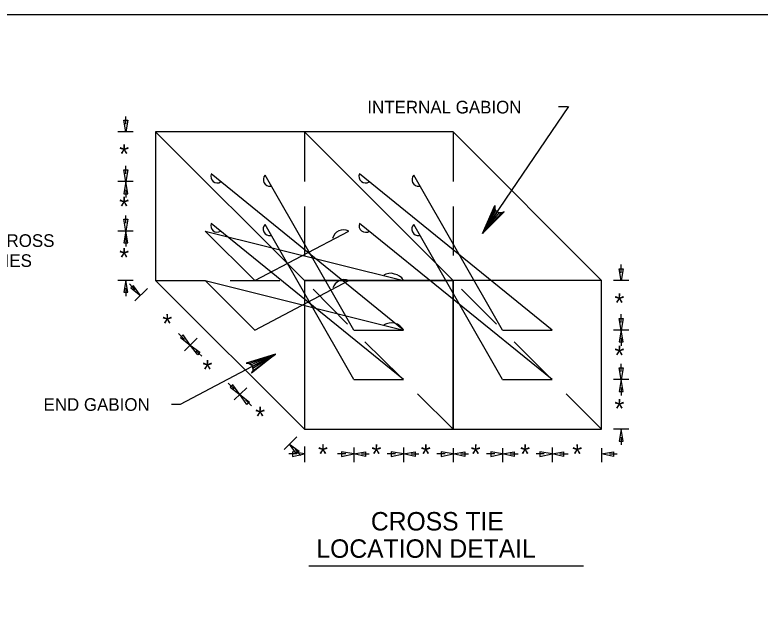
# Model space of a CAD drawing. Extents: x 3 to 3592, y -602 to 1171.
# Drawn here: x 1086.4 to 1263.1, y 421.8 to 561.8 of the extents above; entities that cross this region are included whole.
import ezdxf

# ---------------------------------------------------------------- set-up
doc = ezdxf.new("R2010")
doc.units = 0
for name, color, linetype in [('1', 7, 'Continuous'), ('2', 7, 'Continuous'), ('3', 7, 'Continuous'), ('H', 7, 'Continuous'), ('P', 7, 'Continuous')]:
    doc.layers.add(name, color=color, linetype=linetype)

msp = doc.modelspace()

# ---------------------------------------------------------------- linework, layer by layer
at = {"layer": '1'}
msp.add_lwpolyline([(1668.51, -2.17), (1668.51, 561.83), (882.51, 561.83), (882.51, -2.17), (1668.51, -2.17), (1668.51, 24.19), (1468.51, 24.19), (1468.51, 88.87), (1668.51, 88.87), (1668.51, 117.83), (1468.51, 117.83), (1468.51, -2.17), (1547.31, -2.17), (1547.31, 24.19), (1547.31, -2.17), (1624.31, -2.17), (1624.31, 24.19), (1624.31, 11.88), (1668.51, 11.88)], dxfattribs=at)
for centre, radius, start, end in [((1134.36, 523.51), 1.53, 160.1506, 301.2706), ((1146.84, 522.74), 1.57, 135.9148, 277.2153), ((1169.56, 523.55), 1.6, 158.8193, 302.0614), ((1182.1, 522.74), 1.57, 135.9148, 277.2153), ((1134.36, 511.82), 1.53, 160.1506, 301.2706), ((1146.79, 511.02), 1.55, 133.6678, 279.4623), ((1164.28, 508.18), 2.66, 61.7948, 166.7649), ((1169.55, 511.83), 1.57, 160.8674, 303.0386), ((1182.04, 511.02), 1.55, 133.6678, 279.4623), ((1164.5, 496.2), 2.83, 68.5264, 162.5936), ((1175.62, 485.43), 3.34, 28.9849, 121.7734)]:
    msp.add_arc(centre, radius, start, end, dxfattribs=at)
at = {"layer": '2'}
for points in [[(1197.29, 509.96), (1200.19, 516.61), (1200.2, 515.94), (1197.29, 509.96), (1200.43, 515.44), (1200.78, 515.1), (1197.29, 509.96), (1201.22, 514.9), (1201.78, 514.87), (1197.29, 509.96), (1202.4, 515.11), (1201.78, 514.87), (1201.22, 514.9), (1200.78, 515.1), (1200.43, 515.44), (1200.2, 515.94)], [(1148.17, 481.35), (1142.5, 476.82), (1142.81, 477.42), (1148.17, 481.35), (1142.83, 477.97), (1142.68, 478.43), (1148.17, 481.35), (1142.39, 478.82), (1141.91, 479.11), (1148.17, 481.35), (1141.25, 479.19), (1141.91, 479.11), (1142.39, 478.82), (1142.68, 478.43), (1142.83, 477.97), (1142.81, 477.42)]]:
    msp.add_lwpolyline(points, dxfattribs=at)
at = {"layer": '3'}
msp.add_line((1156.11, 431.12), (1221.23, 431.12), dxfattribs=at)
at = {"layer": 'H'}
for p, q in [((1112.24, 536.83), (1113.16, 536.83)), ((1112.7, 534.09), (1112.24, 536.83)), ((1113.16, 536.83), (1112.7, 534.09)), ((1112.24, 525.04), (1113.16, 525.04)), ((1112.7, 522.3), (1112.24, 525.04)), ((1113.16, 525.04), (1112.7, 522.3)), ((1112.7, 522.3), (1112.24, 519.41)), ((1113.16, 519.41), (1112.7, 522.3)), ((1112.24, 519.41), (1113.16, 519.41)), ((1112.24, 513.41), (1113.16, 513.41)), ((1112.7, 510.52), (1112.24, 513.41)), ((1113.16, 513.41), (1112.7, 510.52)), ((1112.7, 510.52), (1112.24, 507.77)), ((1113.16, 507.77), (1112.7, 510.52)), ((1112.24, 507.77), (1113.16, 507.77)), ((1229.69, 501.58), (1230.61, 501.58)), ((1230.15, 498.83), (1229.69, 501.58)), ((1230.61, 501.58), (1230.15, 498.83)), ((1112.7, 498.83), (1112.24, 496.09)), ((1113.16, 496.09), (1112.7, 498.83)), ((1114.48, 497.55), (1113.87, 497.1)), ((1113.87, 497.1), (1116.16, 495.27)), ((1116.16, 495.27), (1114.48, 497.55)), ((1112.24, 496.09), (1113.16, 496.09)), ((1229.69, 489.79), (1230.61, 489.79)), ((1230.15, 487.05), (1229.69, 489.79)), ((1230.61, 489.79), (1230.15, 487.05)), ((1230.15, 487.05), (1229.69, 484.3)), ((1230.61, 484.3), (1230.15, 487.05)), ((1126.26, 485.93), (1125.65, 485.32)), ((1125.65, 485.32), (1127.94, 483.49)), ((1127.94, 483.49), (1126.26, 485.93)), ((1229.69, 484.3), (1230.61, 484.3)), ((1129.77, 481.2), (1127.94, 483.49)), ((1127.94, 483.49), (1130.23, 481.81)), ((1130.23, 481.81), (1129.77, 481.2)), ((1229.69, 478.11), (1230.61, 478.11)), ((1230.15, 475.36), (1229.69, 478.11)), ((1230.61, 478.11), (1230.15, 475.36)), ((1138.05, 474.09), (1137.44, 473.48)), ((1139.72, 471.81), (1138.05, 474.09)), ((1230.15, 475.36), (1229.69, 472.47)), ((1230.61, 472.47), (1230.15, 475.36)), ((1137.44, 473.48), (1139.72, 471.81)), ((1229.69, 472.47), (1230.61, 472.47)), ((1141.4, 469.37), (1139.72, 471.81)), ((1139.72, 471.81), (1142.01, 469.98)), ((1142.01, 469.98), (1141.4, 469.37)), ((1230.15, 463.58), (1229.69, 460.68)), ((1230.61, 460.68), (1230.15, 463.58)), ((1153.19, 457.73), (1151.51, 460.02)), ((1151.51, 460.02), (1153.8, 458.34)), ((1229.69, 460.68), (1230.61, 460.68)), ((1152.17, 458.14), (1152.17, 457.07)), ((1155.07, 457.68), (1152.17, 458.14)), ((1153.8, 458.34), (1153.19, 457.73)), ((1163.85, 458.14), (1163.85, 457.07)), ((1166.75, 457.68), (1163.85, 458.14)), ((1166.75, 457.68), (1169.49, 458.14)), ((1169.49, 458.14), (1169.49, 457.07)), ((1175.64, 458.14), (1175.64, 457.07)), ((1178.54, 457.68), (1175.64, 458.14)), ((1178.54, 457.68), (1181.28, 458.14)), ((1181.28, 458.14), (1181.28, 457.07)), ((1187.43, 458.14), (1187.43, 457.07)), ((1190.32, 457.68), (1187.43, 458.14)), ((1190.32, 457.68), (1193.06, 458.14)), ((1193.06, 458.14), (1193.06, 457.07)), ((1199.26, 458.14), (1199.26, 457.07)), ((1202.01, 457.68), (1199.26, 458.14)), ((1202.01, 457.68), (1204.75, 458.14)), ((1204.75, 458.14), (1204.75, 457.07)), ((1210.9, 458.14), (1210.9, 457.07)), ((1213.79, 457.68), (1210.9, 458.14)), ((1213.78, 457.68), (1216.52, 458.14)), ((1216.52, 458.14), (1216.52, 457.07)), ((1225.48, 457.68), (1228.37, 458.14)), ((1228.37, 458.14), (1228.37, 457.07)), ((1152.17, 457.07), (1155.07, 457.68)), ((1163.85, 457.07), (1166.75, 457.68)), ((1169.49, 457.07), (1166.75, 457.68)), ((1175.64, 457.07), (1178.54, 457.68)), ((1181.28, 457.07), (1178.54, 457.68)), ((1187.43, 457.07), (1190.32, 457.68)), ((1193.06, 457.07), (1190.32, 457.68)), ((1199.26, 457.07), (1202.01, 457.68)), ((1204.75, 457.07), (1202.01, 457.68)), ((1210.9, 457.07), (1213.79, 457.68)), ((1216.52, 457.07), (1213.78, 457.68)), ((1228.37, 457.07), (1225.48, 457.68))]:
    msp.add_line(p, q, dxfattribs=at)
at = {"layer": 'P'}
for points in [[(1197.29, 509.96), (1217.75, 540.08)], [(1215.32, 540.08), (1217.45, 540.08)], [(1112.7, 535.92), (1112.7, 537.74)], [(1114.43, 534.09), (1110.77, 534.09)], [(1155.07, 534.09), (1119.71, 534.09)], [(1119.71, 534.09), (1119.71, 498.83)], [(1119.71, 534.09), (1155.07, 498.83)], [(1190.32, 534.09), (1155.07, 534.09)], [(1155.07, 534.09), (1190.32, 498.83)], [(1155.07, 534.09), (1155.07, 522.3)], [(1190.32, 534.09), (1225.48, 498.83)], [(1190.32, 534.09), (1190.32, 522.3)], [(1112.7, 524.13), (1112.7, 526.06)], [(1178.54, 487.05), (1132.92, 524.13)], [(1166.75, 487.05), (1145.72, 523.83)], [(1213.79, 487.05), (1168.07, 524.13)], [(1202.01, 487.05), (1180.97, 523.83)], [(1114.43, 522.3), (1110.77, 522.3)], [(1114.43, 522.3), (1110.77, 522.3)], [(1112.7, 520.37), (1112.7, 518.54)], [(1155.07, 516.41), (1155.07, 504.72)], [(1190.32, 516.41), (1190.32, 504.72)], [(1112.7, 512.45), (1112.7, 514.28)], [(1178.54, 475.36), (1132.92, 512.34)], [(1166.75, 475.36), (1145.72, 512.14)], [(1213.79, 475.36), (1168.07, 512.34)], [(1202.01, 475.36), (1180.97, 512.14)], [(1114.43, 510.52), (1110.77, 510.52)], [(1114.43, 510.52), (1110.77, 510.52)], [(1112.7, 510.52), (1112.7, 506.86)], [(1143.28, 498.83), (1131.5, 510.52)], [(1131.5, 510.52), (1178.54, 498.83)], [(1143.28, 498.83), (1165.53, 510.52)], [(1230.15, 500.66), (1230.15, 502.59)], [(1178.54, 498.83), (1178.13, 499.44), (1177.62, 499.85), (1177.01, 500.15), (1176.4, 500.36), (1175.69, 500.56), (1175.08, 500.46), (1174.37, 500.36), (1173.86, 500.05)], [(1114.43, 498.83), (1110.77, 498.83)], [(1119.71, 498.83), (1155.07, 463.58)], [(1119.71, 498.83), (1131.5, 498.83)], [(1143.28, 487.05), (1131.5, 498.83)], [(1131.5, 498.83), (1178.54, 487.05)], [(1137.39, 498.83), (1149.17, 498.83)], [(1143.28, 487.05), (1165.53, 498.83)], [(1190.32, 498.83), (1155.07, 498.83)], [(1155.07, 498.83), (1155.07, 463.58)], [(1155.07, 498.83), (1190.32, 498.83)], [(1190.32, 463.58), (1190.32, 498.83)], [(1225.48, 498.83), (1190.32, 498.83)], [(1190.32, 498.83), (1190.32, 463.58)], [(1225.48, 463.58), (1225.48, 498.83)], [(1231.98, 498.83), (1228.32, 498.83)], [(1112.7, 497), (1112.7, 495.07)], [(1114.83, 496.6), (1113.51, 498.02)], [(1117.78, 496.9), (1114.83, 493.96)], [(1165.23, 488.47), (1157.1, 496.8)], [(1200.58, 488.47), (1192.25, 496.8)], [(1230.15, 488.88), (1230.15, 490.81)], [(1126.62, 484.81), (1125.2, 486.23)], [(1166.75, 487.05), (1178.54, 487.05)], [(1202.01, 487.05), (1213.79, 487.05)], [(1231.98, 487.05), (1228.32, 487.05)], [(1231.98, 487.05), (1228.32, 487.05)], [(1129.56, 485.12), (1126.62, 482.17)], [(1177.72, 476.07), (1169.39, 484.3)], [(1212.98, 476.07), (1204.75, 484.3)], [(1230.15, 485.22), (1230.15, 483.29)], [(1128.24, 483.8), (1126.62, 482.17)], [(1148.17, 481.35), (1125.6, 469.37)], [(1129.26, 482.17), (1130.68, 480.85)], [(1230.15, 477.19), (1230.15, 479.02)], [(1138.4, 473.13), (1136.98, 474.45)], [(1166.75, 475.36), (1178.54, 475.36)], [(1202.01, 475.36), (1213.79, 475.36)], [(1231.98, 475.36), (1228.32, 475.36)], [(1231.98, 475.36), (1228.32, 475.36)], [(1141.35, 473.33), (1138.4, 470.49)], [(1190.32, 463.58), (1181.89, 471.91)], [(1225.48, 463.58), (1217.14, 471.91)], [(1230.15, 473.43), (1230.15, 471.5)], [(1141.05, 470.49), (1142.47, 469.06)], [(1125.6, 469.37), (1123.47, 469.37)], [(1155.07, 463.58), (1190.32, 463.58)], [(1190.32, 463.58), (1225.48, 463.58)], [(1231.98, 463.58), (1228.32, 463.58)], [(1153.24, 461.75), (1150.19, 458.7)], [(1230.15, 461.65), (1230.15, 459.82)], [(1152.83, 458.7), (1154.15, 457.28)], [(1155.07, 459.41), (1155.07, 455.75)], [(1166.75, 459.21), (1166.75, 455.75)], [(1178.54, 459.21), (1178.54, 455.75)], [(1190.32, 459), (1190.32, 455.75)], [(1202.01, 459), (1202.01, 455.75)], [(1213.79, 459.21), (1213.79, 455.75)], [(1225.48, 459), (1225.48, 455.75)], [(1153.14, 457.68), (1151.31, 457.68)], [(1164.82, 457.68), (1162.89, 457.68)], [(1166.75, 457.07), (1166.75, 455.75)], [(1168.58, 457.68), (1170.41, 457.68)], [(1176.61, 457.68), (1174.68, 457.68)], [(1178.54, 457.07), (1178.54, 455.75)], [(1180.36, 457.68), (1182.19, 457.68)], [(1188.39, 457.68), (1186.46, 457.68)], [(1190.32, 457.07), (1190.32, 455.75)], [(1192.15, 457.68), (1193.98, 457.68)], [(1200.18, 457.68), (1198.25, 457.68)], [(1202.01, 457.07), (1202.01, 455.75)], [(1203.83, 457.68), (1205.76, 457.68)], [(1211.86, 457.68), (1210.03, 457.68)], [(1213.79, 457.07), (1213.79, 455.75)], [(1215.62, 457.68), (1217.55, 457.68)], [(1227.41, 457.68), (1229.23, 457.68)]]:
    msp.add_lwpolyline(points, dxfattribs=at)

# ---------------------------------------------------------------- texts
at = {"layer": '3'}
for s, height, p in [('INTERNAL GABION', 3, (1169.96, 538.45)), ('*', 4.5, (1111.1, 526.61)), ('*', 4.5, (1111.1, 514.18)), ('CROSS', 3, (1081.48, 506.79)), ('*', 4.5, (1111.1, 502.05)), ('TIES', 3, (1081.48, 502.04)), ('*', 4.5, (1228.57, 491.28)), ('*', 4.5, (1121.33, 486.37)), ('*', 4.5, (1228.57, 478.85)), ('*', 4.5, (1130.86, 475.48)), ('END GABION', 3, (1093.15, 467.9)), ('*', 4.5, (1228.57, 466.19)), ('*', 4.5, (1143.35, 464.35)), ('*', 4.5, (1158.26, 455.42)), ('*', 4.5, (1170.93, 455.42)), ('*', 4.5, (1182.65, 455.42)), ('*', 4.5, (1194.48, 455.42)), ('*', 4.5, (1206.2, 455.42)), ('*', 4.5, (1218.57, 455.42)), ('CROSS TIE', 4.375, (1170.8, 439.51)), ('LOCATION DETAIL', 4.375, (1157.88, 433.03))]:
    msp.add_text(s, height=height, dxfattribs=at).set_placement(p)

doc.saveas('drawing.dxf')
